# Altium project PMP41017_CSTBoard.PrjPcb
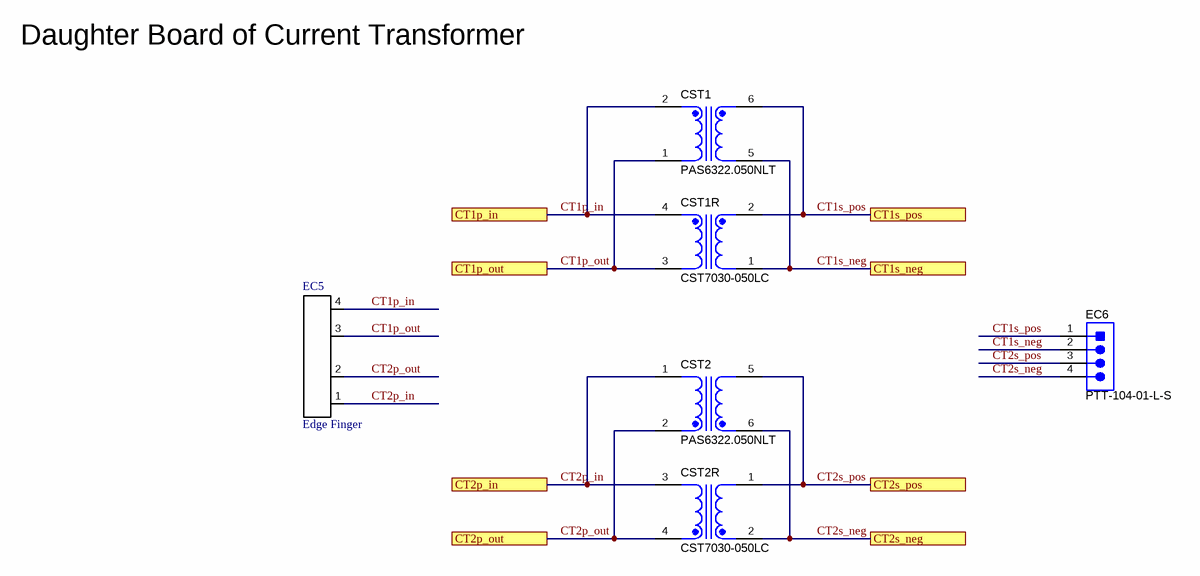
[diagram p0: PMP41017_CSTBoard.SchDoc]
CopyrightYear: 2022; EVM_orderable: Not orderable; PCB_Layout: Desheng Guo; PCB_Rev: E1; PRJ_Customer: Public Release; PRJ_Engineer: Desheng Guo; PRJ_Number: PMP41017; PRJ_Title: CRPS 12V 3000W LLC CST Board; SCH_Rev: E1; TechSupport: http://www.ti.com/support; TID: PMP41017
1 sheet, 6 parts. Net scope: flat (ports and power ports of the same name join across sheets).
Board file: PMP41017_CSTBoard.PcbDoc

## Sheet PMP41017_CSTBoard.SchDoc: PMP41017 CST Board
size A4; Date: Not shown in title block; ApprovedBy: Not shown in title block; CheckedBy: Not shown in title block; Author: Not shown in title block; CompanyName: Not shown in title block; DrawnBy: Desheng Guo; Engineer: Not shown in title block; Organization: Not shown in title block; Address1: Not shown in title block; Address2: Not shown in title block; Address3: Not shown in title block; Address4: Not shown in title block; DocumentNumber: 1; Revision: Use project parameter SCH_Rev; SheetNumber: 1; SheetTotal: 1; PageSetup: Record=PageOptions¦CenterHorizontal=True¦CenterVertical=True¦PrintScale=0.93¦XCorrection=1.00¦YCorrection=1.00¦PrintKind=0¦BorderSize=5000000¦LeftOffset=0¦BottomOffset=0¦Orientation=2¦PaperLength=1000¦PaperWidth=1000¦Scale=100¦PaperSource=15¦PrintQuality=600¦MediaType=1¦DitherType=10¦PaperKind=Letter¦PrintScaleMode=1

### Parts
CST1  PAS6322.050NLT  [Pulse_PAS6322]
CST1R  CST7030-050LC  [Coilcraft_CST7030]
CST2  PAS6322.050NLT  [Pulse_PAS6322]
CST2R  CST7030-050LC  [Coilcraft_CST7030]
EC5  Edge Finger  [EC_CST]  (no BOM)
EC6  PTT-104-01-L-S  [Samtec_PTT-104-01-x-S]  (no BOM)

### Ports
CT1p_in, CT1p_out, CT1s_neg, CT1s_pos, CT2p_in, CT2p_out, CT2s_neg, CT2s_pos

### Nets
CT1p_in: CST1.2 CST1R.4 EC5.4 ; port CT1p_in
CT1p_out: CST1.1 CST1R.3 EC5.3 ; port CT1p_out
CT1s_neg: CST1.5 CST1R.1 EC6.2 ; port CT1s_neg
CT1s_pos: CST1.6 CST1R.2 EC6.1 ; port CT1s_pos
CT2p_in: CST2.1 CST2R.3 EC5.1 ; port CT2p_in
CT2p_out: CST2.2 CST2R.4 EC5.2 ; port CT2p_out
CT2s_neg: CST2.6 CST2R.2 EC6.4 ; port CT2s_neg
CT2s_pos: CST2.5 CST2R.1 EC6.3 ; port CT2s_pos

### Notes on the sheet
- Daughter Board of Current Transformer

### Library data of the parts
CST1 CST2 = Coilcraft_CST7030: Current Sense Transformer, 1100uH, SMT; Manufacturer: Pulse; SizeAreaWB_mm2: 64.8; DCR_ohm: 1.5m; Lp: 1100; SizeZ_mm: 7.0; SizeX_mm: 20.5; SizeY_mm: 12.8; Ns1toNp: 50; SizeArea_mm2: 36.4; Ind_H: 1100µH; Rsec1_ohm: 0.6
CST1R CST2R = CMP-0030157-2: Current Sense Transformer, 333uH, SMT; Manufacturer: Coilcraft; SizeAreaWB_mm2: 64.8; DCR_ohm: 1.5m; Lp: 333; SizeZ_mm: 3; SizeX_mm: 7; SizeY_mm: 5.2; Ns1toNp: 50; SizeArea_mm2: 36.4; Ind_H: 333µH; Rsec1_ohm: 2.76
EC5 = EC_CT: Edge Finger of CT board
EC6 = CMP-0055572-1: Header, 2mm, 4x1, Gold, TH; Manufacturer: Samtec; CNHeader: TRUE; Current_A: 2.9A; Shrouded: N; Gender: Male; Row_Count: 1; Pitch_mm: 2; CT: FALSE; Cert_UL: Y

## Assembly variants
001: not fitted FID1 FID2 FID3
